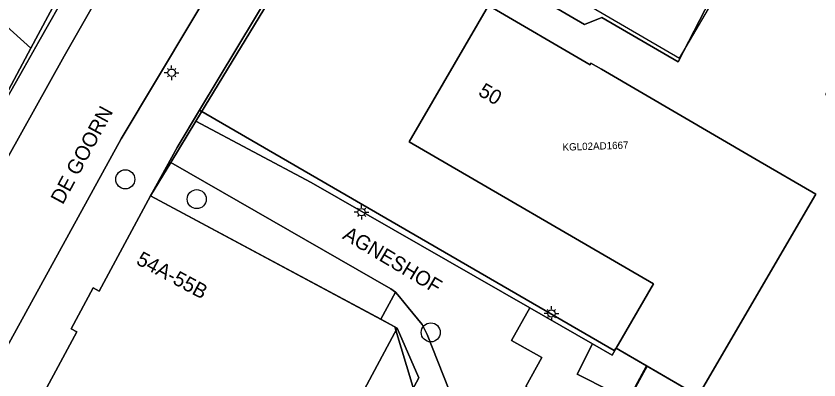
# Model space of a CAD drawing. Extents: x 124901 to 125496, y 515369 to 515789.
# Drawn here: x 125071.7 to 125126.4, y 515599.5 to 515624.4 of the extents above; entities that cross this region are included whole.
import ezdxf

# ---------------------------------------------------------------- set-up
doc = ezdxf.new("R2010")
doc.units = 0
for name, color, linetype in [('Gebouw', 7, 'Continuous'), ('Lichtmast', 7, 'Continuous'), ('Onbegroeid terrein', 7, 'Continuous'), ('Overige bouwwerk', 7, 'Continuous'), ('Parkeren', 7, 'Continuous'), ('Perceelnummers', 7, 'Continuous'), ('Perceelsgrenzen', 7, 'Continuous'), ('Putten', 7, 'Continuous'), ('Teksten', 7, 'Continuous'), ('Vegetatie', 7, 'Continuous'), ('Voetpad', 7, 'Continuous'), ('Wegen lokale weg', 7, 'Continuous')]:
    doc.layers.add(name, color=color, linetype=linetype)

msp = doc.modelspace()

# ---------------------------------------------------------------- linework, layer by layer
at = {"layer": 'Gebouw'}
for points in [[(125110.882, 515621.141), (125110.823, 515621.04), (125103.905, 515625.07), (125098.497, 515615.788), (125115.151, 515606.085), (125112.602, 515601.71), (125114.707, 515600.484), (125118.201, 515598.448), (125126.217, 515612.207), (125122.149, 515614.577), (125111.596, 515620.725)], [(125096.563, 515603.671), (125080.84, 515612.087), (125077.359, 515605.589), (125076.944, 515605.812), (125075.449, 515603.021), (125075.821, 515602.821), (125072.515, 515596.65), (125088.951, 515587.846), (125089.369, 515587.622), (125092.923, 515594.233), (125093.889, 515596.029), (125097.677, 515603.075)]]:
    msp.add_lwpolyline(points, close=True, dxfattribs=at)
at = {"layer": 'Lichtmast'}
for p, q in [((125082.077, 515620.706), (125082.007, 515620.777)), ((125082.289, 515620.794), (125082.289, 515620.994)), ((125082.501, 515620.706), (125082.572, 515620.778)), ((125081.989, 515620.495), (125081.789, 515620.494)), ((125082.077, 515620.282), (125082.005, 515620.211)), ((125082.289, 515620.194), (125082.289, 515619.994)), ((125082.501, 515620.282), (125082.571, 515620.211)), ((125082.589, 515620.494), (125082.789, 515620.494)), ((125095.028, 515611.19), (125094.958, 515611.261)), ((125095.24, 515611.278), (125095.24, 515611.478)), ((125095.452, 515611.19), (125095.523, 515611.262)), ((125094.94, 515610.979), (125094.74, 515610.978)), ((125095.028, 515610.766), (125094.956, 515610.695)), ((125095.24, 515610.678), (125095.24, 515610.478)), ((125095.452, 515610.766), (125095.522, 515610.695)), ((125095.54, 515610.978), (125095.74, 515610.978)), ((125107.975, 515604.275), (125107.905, 515604.346)), ((125108.187, 515604.363), (125108.187, 515604.563)), ((125108.399, 515604.275), (125108.47, 515604.347)), ((125107.887, 515604.064), (125107.687, 515604.063)), ((125107.975, 515603.851), (125107.903, 515603.78)), ((125108.187, 515603.763), (125108.187, 515603.563)), ((125108.399, 515603.851), (125108.469, 515603.78)), ((125108.487, 515604.063), (125108.687, 515604.063))]:
    msp.add_line(p, q, dxfattribs=at)
for centre in [(125082.289, 515620.494), (125095.24, 515610.978), (125108.187, 515604.063)]:
    msp.add_circle(centre, 0.25, dxfattribs=at)
at = {"layer": 'Onbegroeid terrein'}
for points in [[(125090.11, 515627.331), (125083.94, 515617.184), (125091.796, 515612.998), (125106.706, 515604.446), (125110.98, 515601.994), (125112.323, 515601.224), (125112.602, 515601.71), (125115.151, 515606.085), (125098.497, 515615.788), (125103.905, 515625.07), (125110.823, 515621.04), (125110.882, 515621.141), (125111.596, 515620.725), (125122.149, 515614.577), (125126.217, 515612.207), (125118.201, 515598.448), (125114.707, 515600.484), (125112.502, 515596.459)], [(125069.519, 515616.097), (125072.2, 515620.809), (125073.228, 515622.617), (125075.311, 515626.278)]]:
    msp.add_lwpolyline(points, dxfattribs=at)
msp.add_lwpolyline([(125091.926, 515586.254), (125095.465, 515592.866), (125099.142, 515599.676), (125097.677, 515603.075), (125093.889, 515596.029), (125092.923, 515594.233), (125089.369, 515587.622)], close=True, dxfattribs=at)
at = {"layer": 'Overige bouwwerk'}
msp.add_lwpolyline([(125116.931, 515621.486), (125119.575, 515626.025), (125113.588, 515629.514), (125110.943, 515624.975)], close=True, dxfattribs=at)
at = {"layer": 'Parkeren'}
for points in [[(125070.056, 515612.85), (125074.966, 515621.628), (125077.049, 515625.289), (125081.443, 515633.011), (125089.462, 515645.498), (125089.281, 515645.41), (125086.621, 515644.747), (125086.531, 515644.661), (125086.43, 515644.565), (125079.729, 515634.043), (125075.311, 515626.278), (125073.228, 515622.617), (125072.2, 515620.809), (125069.519, 515616.097), (125069.537, 515615.75), (125069.565, 515615.51), (125070.086, 515613.465), (125070.15, 515613.216), (125070.135, 515613.049)], [(125111.356, 515597.083), (125112.242, 515598.764), (125109.933, 515599.94), (125110.98, 515601.994), (125106.706, 515604.446), (125105.474, 515602.218), (125107.543, 515601.074), (125106.442, 515599.083), (125107.257, 515598.632), (125107.261, 515598.63), (125111.083, 515596.566)]]:
    msp.add_lwpolyline(points, close=True, dxfattribs=at)
at = {"layer": 'Perceelsgrenzen'}
for points in [[(125040.931, 515627.093), (125037.137, 515630.723), (125036.712, 515631.413), (125031.866, 515639.28), (125034.423, 515641.126), (125026.885, 515653.376), (125023.812, 515658.371), (125019.579, 515665.251), (125016.351, 515670.496), (125013.58, 515690.889), (125023.847, 515691.023), (125024.009, 515686.713), (125031.069, 515680.399), (125080.294, 515636.377), (125072.681, 515622.173), (125060.212, 515633.452), (125055.522, 515628.217), (125053.571, 515626.038), (125048.992, 515620.927), (125048.229, 515620.075), (125048.15, 515620.185), (125046.127, 515622.121)], [(125094.787, 515635.584), (125096.223, 515637.971), (125096.611, 515637.757), (125097.361, 515639.025), (125119.387, 515626.196), (125116.825, 515621.224), (125111.621, 515624.256), (125110.434, 515623.79), (125093.595, 515633.603)], [(125072.681, 515622.173), (125069.998, 515617.166), (125069.468, 515616.178), (125064.966, 515619.218), (125065.039, 515619.326), (125059.078, 515623.201), (125058.681, 515622.614), (125058.582, 515622.681), (125053.571, 515626.038), (125055.522, 515628.217), (125060.212, 515633.452)], [(125087.836, 515585.679), (125086.845, 515583.619), (125082.657, 515585.769), (125083.865, 515587.883), (125071.114, 515594.848), (125072.151, 515596.222), (125072.515, 515596.65), (125075.821, 515602.821), (125075.449, 515603.021), (125076.944, 515605.812), (125077.359, 515605.589), (125080.84, 515612.087), (125097.499, 515603.161), (125098.736, 515599.084), (125091.393, 515585.313), (125088.493, 515586.859)], [(125127.795, 515586.106), (125111.625, 515594.858), (125114.671, 515600.505), (125118.201, 515598.448), (125120.6, 515597.188), (125119.979, 515596.198), (125127.431, 515591.936), (125130.01, 515590.488)]]:
    msp.add_lwpolyline(points, close=True, dxfattribs=at)
for points in [[(125002.221, 515491.957), (125012.299, 515514.356), (125013.576, 515513.702), (125016.718, 515511.968), (125028.241, 515533.814), (125035.799, 515548.142), (125042.332, 515560.528), (125041.613, 515561.12), (125048.213, 515573.798), (125051.878, 515579.322), (125058.053, 515590.876), (125061.843, 515597.969), (125060.771, 515599.949), (125063.483, 515605.009), (125069.468, 515616.178), (125069.998, 515617.166), (125072.681, 515622.173), (125080.294, 515636.377)], [(125093.595, 515633.603), (125110.434, 515623.79), (125111.621, 515624.256), (125116.825, 515621.224), (125119.387, 515626.196)], [(125131.339, 515627.899), (125126.878, 515619.009), (125133.999, 515615.864), (125142.115, 515612.279), (125140.864, 515610.273), (125137.988, 515605.121), (125130.01, 515590.488), (125127.431, 515591.936), (125119.979, 515596.198), (125120.6, 515597.188), (125118.201, 515598.448), (125114.671, 515600.505), (125112.602, 515601.71), (125112.476, 515601.547), (125084.2, 515617.939), (125089.274, 515626.42)], [(125089.274, 515626.42), (125084.2, 515617.939), (125082.671, 515615.383), (125080.84, 515612.087), (125077.359, 515605.589), (125076.944, 515605.812), (125075.449, 515603.021), (125075.821, 515602.821), (125072.515, 515596.65), (125072.151, 515596.222), (125071.114, 515594.848)], [(125098.736, 515599.084), (125097.499, 515603.161), (125080.84, 515612.087), (125082.671, 515615.383), (125084.2, 515617.939), (125112.476, 515601.547), (125112.602, 515601.71), (125114.671, 515600.505), (125111.625, 515594.858)]]:
    msp.add_lwpolyline(points, dxfattribs=at)
at = {"layer": 'Putten'}
for centre in [(125079.13, 515613.22), (125084, 515611.87), (125099.96, 515602.78)]:
    msp.add_circle(centre, 0.65, dxfattribs=at)
at = {"layer": 'Vegetatie'}
for points in [[(125080.84, 515612.087), (125096.563, 515603.671), (125097.552, 515605.518), (125097.244, 515605.741), (125082.226, 515614.366)], [(125112.242, 515598.764), (125111.356, 515597.083), (125112.502, 515596.459), (125114.707, 515600.484), (125112.602, 515601.71), (125112.323, 515601.224), (125110.98, 515601.994), (125109.933, 515599.94)]]:
    msp.add_lwpolyline(points, close=True, dxfattribs=at)
at = {"layer": 'Voetpad'}
for points in [[(125088.561, 515632.219), (125078.852, 515615.982), (125070.405, 515600.661), (125063.124, 515587.005), (125063.031, 515586.827), (125054.863, 515571.187), (125049.305, 515560.251), (125042.974, 515547.797), (125036.236, 515534.141), (125026.086, 515513.693), (125020.136, 515501.661)], [(125068.935, 515591.958), (125072.515, 515596.65), (125075.821, 515602.821), (125075.449, 515603.021), (125076.944, 515605.812), (125077.359, 515605.589), (125080.84, 515612.087), (125082.226, 515614.366), (125083.94, 515617.184), (125090.11, 515627.331)], [(125094.079, 515583.208), (125095.717, 515584.862), (125095.962, 515585.279), (125094.034, 515586.395), (125097.031, 515592.084), (125099.239, 515590.896), (125100.706, 515593.519), (125101.159, 515594.431), (125101.347, 515594.754), (125101.446, 515595.131), (125101.643, 515597.168), (125101.631, 515597.528), (125101.551, 515597.965), (125099.709, 515602.645), (125099.499, 515603.035), (125099.371, 515603.312), (125098.43, 515604.476), (125097.837, 515605.211), (125097.552, 515605.518), (125096.563, 515603.671)], [(125096.563, 515603.671), (125097.677, 515603.075), (125099.142, 515599.676), (125095.465, 515592.866), (125091.926, 515586.254), (125089.369, 515587.622), (125088.951, 515587.846), (125088.003, 515586.074), (125089.175, 515585.469), (125093.575, 515583.196)]]:
    msp.add_lwpolyline(points, dxfattribs=at)
at = {"layer": 'Wegen lokale weg'}
msp.add_lwpolyline([(125063.124, 515587.005), (125070.405, 515600.661), (125078.852, 515615.982), (125088.561, 515632.219), (125092.011, 515637.687), (125096.857, 515644.957), (125091.656, 515648.529), (125089.696, 515645.675), (125089.591, 515645.587), (125089.462, 515645.498), (125081.443, 515633.011), (125077.049, 515625.289), (125074.966, 515621.628), (125070.056, 515612.85), (125065.259, 515604.145), (125064.885, 515603.466), (125062.379, 515598.744), (125058.023, 515590.533), (125057.609, 515589.753), (125063.031, 515586.827)], close=True, dxfattribs=at)
msp.add_lwpolyline([(125106.442, 515599.083), (125107.543, 515601.074), (125105.474, 515602.218), (125106.706, 515604.446), (125091.796, 515612.998), (125083.94, 515617.184), (125082.226, 515614.366), (125097.244, 515605.741), (125097.552, 515605.518), (125097.837, 515605.211), (125098.43, 515604.476), (125099.371, 515603.312), (125099.499, 515603.035), (125099.709, 515602.645), (125101.551, 515597.965)], dxfattribs=at)

# ---------------------------------------------------------------- texts
at = {"layer": 'Perceelnummers'}
msp.add_text('KGL02AD1667', height=0.5, rotation=1.8293, dxfattribs=at).set_placement((125108.952, 515615.168))
at = {"layer": 'Teksten'}
for s, rotation, p in [('50', 329.8, (125103.134, 515618.987)), ('DE GOORN', 61.6, (125074.863, 515611.449)), ('AGNESHOF', 329.2, (125093.88, 515609.21)), ('54A-55B', 331.8, (125079.805, 515607.472))]:
    msp.add_text(s, height=1, rotation=rotation, dxfattribs=at).set_placement(p)

doc.saveas('drawing.dxf')
